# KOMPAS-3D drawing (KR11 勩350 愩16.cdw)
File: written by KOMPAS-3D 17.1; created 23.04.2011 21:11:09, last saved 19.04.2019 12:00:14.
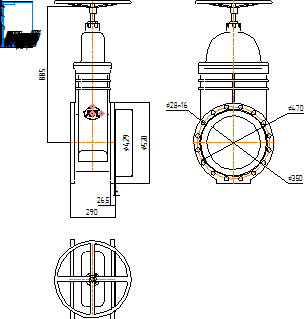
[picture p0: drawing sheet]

Sheet 1: A4, portrait

Title block, sheet 1: name: KR11 Ду350 Ру16; material: Внимание! Данный продукт является объектом авторского права ООО «Торговый Дом АДЛ». / Запрещается изменение, копирование, распространение / (в том числе путем копирования на другие сайты и ресурсы в Интернете) / или любое иное использование информации и объектов без предварительного / согласия правообладателя (ООО «Торговый Дом АДЛ»).; scale: 1:1; sheets: 1; organisation: ООО "Торговый дом АДЛ"; sheet format: A4; stored path: \\adlc.lan\data\АДЛ_ПКД\3D-модели\ADL production\Клиновые задвижки серии KR ГРАНАР\Клиновые задвижки KR11\KOMPAS 2D\KR11 Ду350 Ру16.cdw

Views: Спереди 4, Проекционный вид 5, Проекционный вид 6
Dimensions and other numbers on the sheet: 290; 26,5; 4; 885; 429; 520; 470; 28; 350; 1:1; 1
